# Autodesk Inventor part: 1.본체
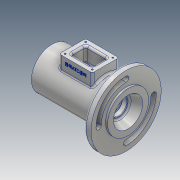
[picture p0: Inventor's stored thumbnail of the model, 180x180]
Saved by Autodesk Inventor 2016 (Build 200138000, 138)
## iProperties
Created: 2017-05
Part Number: 1.본체
Material: 알루미늄 6061
Document SubType Name: Modeling
Designer: Administrator
Density: 2.7 g/cm^3
Appearance: 알루미늄 - 평지
Mass: 676.802 g
Surface Area: 615.016 cm^2
Volume: 250.667 cm^3
Author: Administrator
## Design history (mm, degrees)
sketch "스케치1"
  geometry: L1 (-56, 31)-(59, 31); L2 (59, 31)-(59, 0); L3 (59, 0)-(-56, 0); L4 (-56, 0)-(-56, 31); L5 (56, 0)-(46, 0); L6 (46, 0)-(46, 53); L7 (46, 53)-(56, 53); L8 (56, 53)-(56, 0); 1 further point
  constraints: 16 end point, 4 parallel, 2 horizontal, 2 perpendicular, 2 point on line
  dimensions: "d0" = 115 distance of L1.start L1.end; "d1" = 62 diameter of L1 L3; "d2" = 13 distance between parallel lines of L2 L6; "d3" = 3 distance between parallel lines of L2 L8; "d4" = 106 diameter of L7 L3; "d5" = 56 distance from line of point (0, 0) L4
revolve "회전1" sketch "스케치1" stored, may be unused: angle "d6" = 90 deg
node "작업 평면1"
sketch "스케치2"
  geometry: L1 (-25, -20)-(25, -20); L2 (25, -20)-(25, 20); L3 (25, 20)-(-25, 20); L4 (-25, 20)-(-25, -20); L5 (-25, -20)-(25, 20); L6 (25, -20)-(-25, 20); 1 further point
  constraints: 12 end point, 2 midpoint, 2 parallel, 1 horizontal, 1 perpendicular
  dimensions: "d8" = 50 distance of L2.end L3.end; "d9" = 40 distance of L3.end L1.start
extrude "돌출1" join sketch "스케치2" stored distance "d10" = 10; taper "d11" = 0 deg
sketch "스케치3"
  geometry: L1 (-56, -31)-(-59, -31) reference; L2 (-59, -31)-(-59, 31) reference; L3 (-59, 31)-(-56, 31) reference; L4 (-56, 31)-(-56, 53) reference; L5 (-56, 53)-(-46, 53) reference; L6 (-46, 53)-(-46, 31) reference; L7 (-46, 31)-(-25, 31) reference; L8 (-25, 31)-(-25, 44) reference; L9 (-25, 44)-(25, 44) reference; L10 (25, 44)-(25, 31) reference; L11 (25, 31)-(56, 31) reference; L12 (56, 31)-(56, -31) reference; L13 (56, -31)-(-46, -31) reference; L14 (-46, -31)-(-46, -53) reference; L15 (-46, -53)-(-56, -53) reference; L16 (-56, -53)-(-56, -31) reference; L17 (56, 0)-(-59, 0); L18 (56, 0)-(47, 0); L19 (47, 0)-(47, 21); L20 (47, 21)-(56, 21); L21 (56, 21)-(56, 0); L22 (47, 0)-(44, 0); L23 (44, 0)-(44, 24); L24 (44, 24)-(47, 24); L25 (47, 24)-(47, 0); L26 (44, 0)-(35, 0); L27 (35, 0)-(35, 20); L28 (35, 20)-(44, 20); L29 (44, 20)-(44, 0); L30 (35, 0)-(31.75, 0); L31 (31.75, 0)-(31.75, 17.5); L32 (31.75, 17.5)-(35, 17.5); L33 (35, 17.5)-(35, 0); L34 (31.75, 0)-(30, 0); L35 (30, 0)-(30, 18.5); L36 (30, 18.5)-(31.75, 18.5); L37 (31.75, 18.5)-(31.75, 0); L38 (30, 0)-(19, 0); L39 (19, 0)-(19, 17.5); L40 (19, 17.5)-(30, 17.5); L41 (30, 17.5)-(30, 0); L42 (19, 0)-(-19, 0); L43 (-19, 0)-(-19, 23); L44 (-16, 26)-(16, 26); L45 (19, 23)-(19, 0); L46 (-19, 0)-(-30, 0); L47 (-30, 0)-(-30, 17.2); L48 (-29.7, 17.5)-(-19, 17.5); L49 (-19, 17.5)-(-19, 0); L50 (-30, 0)-(-35, 0); L51 (-35, 0)-(-35, 13.5); L52 (-32, 16.5)-(-30, 16.5); L53 (-30, 16.5)-(-30, 0); L54 (-35, 0)-(-37.7, 0); L55 (-37.7, 0)-(-37.7, 10); L56 (-37.7, 10)-(-35, 10); L57 (-35, 10)-(-35, 0); L58 (-37.7, 0)-(-45, 0); L59 (-45, 0)-(-45, 12.5); L60 (-45, 12.5)-(-38, 12.5); L61 (-37.7, 12.2)-(-37.7, 0); L62 (-45, 0)-(-59, 0); L63 (-59, 0)-(-59, 22); L64 (-59, 22)-(-46.818, 16.779)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; A1 r 3 centre (16, 23) between (19, 23) and (16, 26); A2 r 3 centre (-16, 23) between (-16, 26) and (-19, 23); A3 r 3 centre (-32, 13.5) between (-32, 16.5) and (-35, 13.5); A4 r 3 centre (-48, 14.022) between (-45, 14.022) and (-46.818, 16.779); A5 r 0.3 centre (-29.7, 17.2) between (-29.7, 17.5) and (-30, 17.2); A6 r 0.3 centre (-38, 12.2) between (-37.7, 12.2) and (-38, 12.5); 5 further points
  constraints: 98 end point, 23 parallel, 12 horizontal, 12 perpendicular, 12 point on circle, 12 tangent, 9 point on line, 6 centre point, 3 equal radius, 2 collinear, 2 midpoint
  dimensions: "d12" = 12 distance between parallel lines of L23 L12; "d13" = 3 distance between parallel lines of L29 L19; "d14" = 21 distance between parallel lines of L27 L12; "d15" = 26 distance between parallel lines of L35 L21; "d16" = 1.75 distance of L35.end L36.end; "d17" = 38 distance of point (-19, 26) point (19, 26); "d18" = 60 distance between parallel lines of L47 L35; "d19" = 5 distance between parallel lines of L47 L51; "d20" = 14 distance between parallel lines of L65 L2; "d21" = 11 distance of point (-30, 17.5) L48.end; "d22" = 2.7 distance between parallel lines of L51 L55; "d23" = 42 diameter of L20 L17; "d24" = 48 diameter of L24 L22; "d25" = 40 diameter of L28 L17; "d26" = 35 diameter of L32 L30; "d27" = 37 diameter of L36 L17; "d28" = 52 diameter of L44 L42; "d29" = 35 diameter of L48 L46; "d30" = 33 diameter of L52 L17; "d31" = 20 diameter of L56 L17; "d32" = 25 diameter of L60 L17; "d33" = 32 diameter of point (-45, 16) L17; "d34" = 44 diameter of L63.end L17; "d35" = 3 radius of A1; "d36" = 0.3 radius of A5; "d37" = 0.3 radius of A6
revolve "회전2" sketch "스케치3" stored, may be unused: angle "d38" = 90 deg
node "작업 평면4"
  node "작업 평면3"
sketch "스케치5"
  geometry: L1 (-56, -31)-(-56, 31) reference; L2 (-25, 44)-(25, 44) reference; 2 further points
  constraints: 1 other
  dimensions: "d42" = 56 distance from line of point (0, 36) L1; "d43" = 8 distance from line of point (0, 36) L2
feature "엠보싱1" sketch "스케치5" dims "d0" = 115, "d1" = 62, "d2" = 13, "d3" = 3, "d4" = 106, "d5" = 56, "d44" = 0.5, "d45" = 0
sketch "스케치6"
  geometry: L1 (-16, -11)-(16, -11); L2 (16, -11)-(16, 11); L3 (16, 11)-(-16, 11); L4 (-16, 11)-(-16, -11); L5 (-16, -11)-(16, 11); L6 (16, -11)-(-16, 11); 1 further point
  constraints: 12 end point, 2 midpoint, 2 parallel, 1 horizontal, 1 perpendicular
  dimensions: "d46" = 32 distance of L2.end L3.end; "d47" = 22 distance of L1.end L2.end
extrude "돌출2" cut sketch "스케치6" stored distance "d48" = 10; taper "d49" = 0 deg
fillet "모깎기1" dims "d50" = 3
fillet "모깎기2" dims "d51" = 3
fillet "모깎기3" dims "d52" = 3
sketch "스케치7"
  geometry: L1 (-20.5, -15.5)-(20.5, -15.5); L2 (20.5, -15.5)-(20.5, 15.5); L3 (20.5, 15.5)-(-20.5, 15.5); L4 (-20.5, 15.5)-(-20.5, -15.5); L5 (-20.5, -15.5)-(20.5, 15.5); L6 (20.5, -15.5)-(-20.5, 15.5); 5 further points
  constraints: 12 end point, 4 coincident, 2 midpoint, 2 parallel, 1 horizontal, 1 perpendicular
  dimensions: "d53" = 31 distance of L3.end L1.start; "d54" = 41 distance of L2.end L3.end
hole "구멍1" sketch "스케치7" at (-20.5, 15.5), (20.5, 15.5), (20.5, -15.5), (-20.5, -15.5) diameter "d55" = 2.459; stored, may be unused: countersink angle "d59" = 90 deg, drill point angle "d61" = 118 deg; dims "d56" = 6, "d57" = 4, "d58" = 2, "d60" = 8
sketch "스케치8"
  geometry: L1 (0, -53)-(0, 53); L2 (-53, 0)-(53, 0); A1 r 53 centre (0, 0) between (0, -53) and (0, 53) reference; A2 r 41.5 centre (0, 0) between (0, -41.5) and (-41.5, 0); A3 r 4 centre (0, -41.5) between (0, -45.5) and (0, -37.5); A4 r 4 centre (-41.5, 0) between (-37.5, 0) and (-45.5, 0); A5 r 4 centre (0, 41.5) between (0, 45.5) and (0, 37.5); A6 r 4 centre (41.5, 0) between (37.5, 0) and (45.5, 0); A7 r 37.5 centre (0, 0) between (-37.5, 0) and (0, -37.5); A8 r 37.5 centre (0, 0) between (37.5, 0) and (0, 37.5); A9 r 45.5 centre (0, 0) between (-45.5, 0) and (0, -45.5); A10 r 45.5 centre (0, 0) between (45.5, 0) and (0, 45.5); 2 further points
  constraints: 24 point on circle, 9 centre point, 5 tangent, 4 end point, 4 point on line, 3 coincident, 2 midpoint, 1 horizontal, 1 horizontal alignment, 1 vertical, 1 vertical alignment
  dimensions: "d62" = 83 diameter of A2; "d63" = 8 diameter of A3; "d64" = 8 diameter of A4; "d65" = 45.5 radius of A9; "d66" = 45.5 radius of A10; "d67" = 37.5 radius of A8
extrude "돌출3" cut sketch "스케치8" distance "d68" = 10; taper "d69" = 0 deg
fillet "모깎기4" dims "d70" = 3
chamfer "모따기1" distance "d71" = 0.7; stored, may be unused: second distance "d72" = 2, angle "d73" = 30 deg
chamfer "모따기2" distance "d74" = 1; stored, may be unused: second distance "d75" = 2, angle "d76" = 30 deg
feature "스레드1" dims "d77" = 10, "d78" = 0
chamfer "모따기3" distance "d79" = 1; stored, may be unused: second distance "d80" = 2, angle "d81" = 30 deg
node "솔리드1"
node "절단 모서리 투영1"
other parameters: "d7" = 44, "d40" = 90 deg
